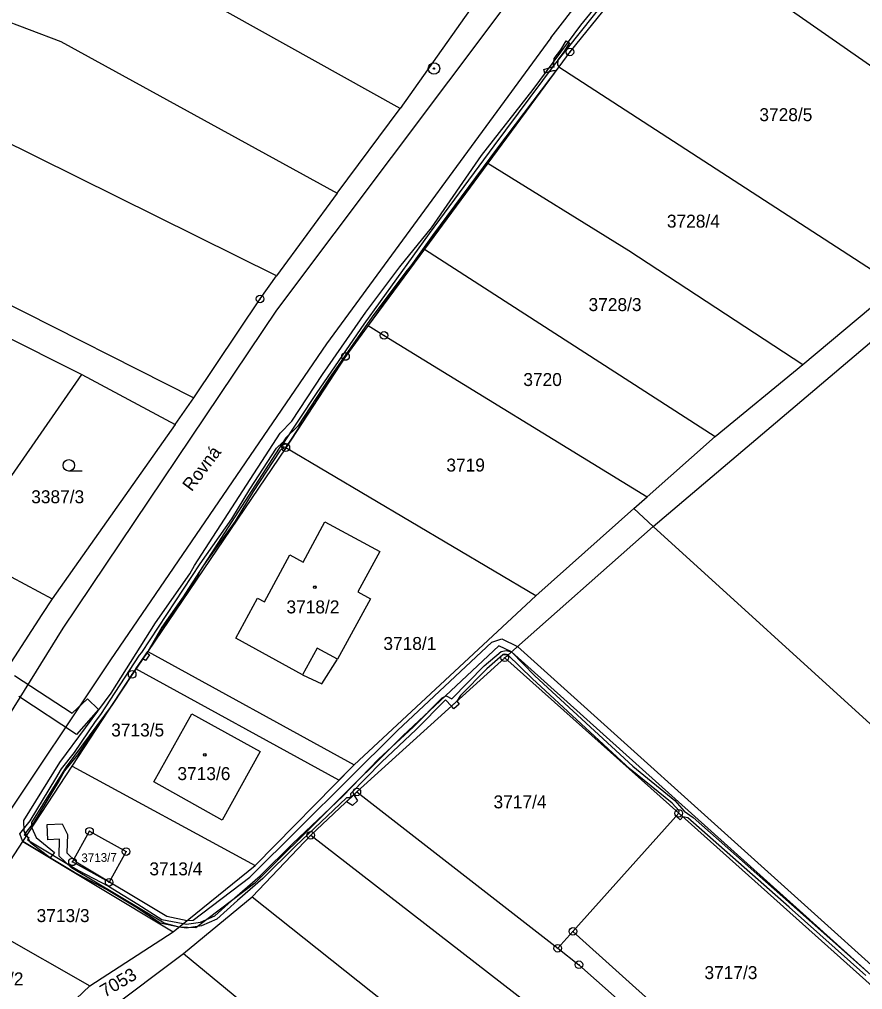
# Model space of a CAD drawing. Extents: x -593183 to -588034, y -1130415 to -1124994.
# Drawn here: x -592268.6 to -592158, y -1128640.9 to -1128513.6 of the extents above; entities that cross this region are included whole.
import ezdxf

# ---------------------------------------------------------------- set-up
doc = ezdxf.new("R2010")
doc.units = 0
for name, color, linetype in [('Vrstva 1', 7, 'Continuous'), ('Vrstva 15', 7, 'Continuous'), ('Vrstva 18', 7, 'Continuous'), ('Vrstva 19', 7, 'Continuous'), ('Vrstva 24', 7, 'Continuous'), ('Vrstva 25', 7, 'Continuous'), ('Vrstva 27', 7, 'Continuous'), ('Vrstva 4', 7, 'Continuous')]:
    doc.layers.add(name, color=color, linetype=linetype)

msp = doc.modelspace()

# ---------------------------------------------------------------- linework, layer by layer
at = {"layer": 'Vrstva 1'}
for p, q in [((-592183.06, -1128501.43), (-592196.37, -1128517.88)), ((-592183.06, -1128501.43), (-592136.79, -1128533.76)), ((-592301.19, -1128502.29), (-592263.16, -1128516.51)), ((-592218.66, -1128525.31), (-592255.87, -1128504.57)), ((-592209.44, -1128512.31), (-592218.66, -1128525.31)), ((-592263.16, -1128516.51), (-592226.91, -1128536.44)), ((-592196.37, -1128517.88), (-592197.82, -1128519.84)), ((-592197.82, -1128519.84), (-592207.12, -1128532.47)), ((-592197.82, -1128519.84), (-592153.49, -1128548.57)), ((-592226.91, -1128536.44), (-592218.66, -1128525.31)), ((-592234.89, -1128547.26), (-592277.87, -1128525.96)), ((-592215.46, -1128543.78), (-592207.12, -1128532.47)), ((-592207.12, -1128532.47), (-592188.62, -1128543.95)), ((-592226.91, -1128536.44), (-592234.89, -1128547.26)), ((-592286.92, -1128542.48), (-592245.72, -1128563.27)), ((-592215.46, -1128543.78), (-592222.84, -1128553.8)), ((-592215.46, -1128543.78), (-592177.29, -1128568.36)), ((-592188.62, -1128543.95), (-592165.79, -1128558.92)), ((-592237.03, -1128550.3), (-592234.89, -1128547.26)), ((-592185.43, -1128580.14), (-592146.62, -1128547.27)), ((-592165.79, -1128558.92), (-592153.49, -1128548.57)), ((-592245.72, -1128563.27), (-592237.03, -1128550.3)), ((-592273.91, -1128553.44), (-592260.44, -1128560.22)), ((-592222.84, -1128553.8), (-592225.82, -1128557.85)), ((-592222.84, -1128553.8), (-592220.76, -1128555.08)), ((-592220.76, -1128555.08), (-592186.23, -1128576.24)), ((-592233.65, -1128569.81), (-592225.82, -1128557.85)), ((-592177.29, -1128568.36), (-592165.79, -1128558.92)), ((-592276.39, -1128583.21), (-592260.44, -1128560.22)), ((-592260.44, -1128560.22), (-592248.17, -1128566.75)), ((-592248.17, -1128566.75), (-592245.72, -1128563.27)), ((-592248.17, -1128566.75), (-592264.34, -1128589.64)), ((-592186.23, -1128576.24), (-592177.29, -1128568.36)), ((-592233.65, -1128569.81), (-592251.78, -1128596.54)), ((-592200.83, -1128589.24), (-592233.65, -1128569.81)), ((-592187.99, -1128577.81), (-592186.23, -1128576.24)), ((-592200.83, -1128589.24), (-592187.99, -1128577.81)), ((-592187.99, -1128577.81), (-592185.43, -1128580.14)), ((-592231.36, -1128584.82), (-592228.53, -1128579.55)), ((-592228.53, -1128579.55), (-592221.32, -1128583.44)), ((-592185.43, -1128580.14), (-592204.92, -1128597.37)), ((-592185.43, -1128580.14), (-592121.56, -1128638.29)), ((-592276.39, -1128583.21), (-592264.34, -1128589.64)), ((-592236.47, -1128590.04), (-592233.11, -1128583.88)), ((-592233.11, -1128583.88), (-592231.36, -1128584.82)), ((-592221.32, -1128583.44), (-592224.21, -1128588.72)), ((-592240.22, -1128594.82), (-592237.36, -1128589.56)), ((-592237.36, -1128589.56), (-592236.47, -1128590.04)), ((-592224.68, -1128611.41), (-592200.83, -1128589.24)), ((-592224.21, -1128588.72), (-592222.54, -1128589.63)), ((-592264.34, -1128589.64), (-592265.68, -1128591.69)), ((-592222.54, -1128589.63), (-592226.88, -1128597.54)), ((-592265.68, -1128591.69), (-592274.2, -1128604.84)), ((-592231.45, -1128599.62), (-592240.22, -1128594.82)), ((-592253.82, -1128599.55), (-592251.78, -1128596.54)), ((-592251.78, -1128596.54), (-592224.68, -1128611.41)), ((-592228.91, -1128600.81), (-592226.88, -1128597.54)), ((-592204.92, -1128597.37), (-592224.33, -1128614.98)), ((-592182.09, -1128617.78), (-592204.92, -1128597.37)), ((-592261.7, -1128611.6), (-592253.82, -1128599.55)), ((-592231.45, -1128599.62), (-592228.91, -1128600.81)), ((-592250.98, -1128613.65), (-592245.98, -1128604.71)), ((-592245.98, -1128604.71), (-592237.02, -1128609.68)), ((-592237.02, -1128609.68), (-592242, -1128618.66)), ((-592268.17, -1128621.49), (-592261.7, -1128611.6)), ((-592261.7, -1128611.6), (-592237.67, -1128624.61)), ((-592237.67, -1128624.61), (-592224.68, -1128611.41)), ((-592242, -1128618.66), (-592250.98, -1128613.65)), ((-592230.38, -1128620.66), (-592224.33, -1128614.98)), ((-592224.33, -1128614.98), (-592197.96, -1128635.49)), ((-592195.97, -1128633.27), (-592182.09, -1128617.78)), ((-592182.09, -1128617.78), (-592153.73, -1128643.13)), ((-592261.65, -1128624.15), (-592259.42, -1128620.13)), ((-592259.42, -1128620.13), (-592254.61, -1128622.8)), ((-592238.07, -1128628.73), (-592230.38, -1128620.66)), ((-592230.38, -1128620.66), (-592200.42, -1128643.81)), ((-592274.81, -1128631.64), (-592268.17, -1128621.49)), ((-592268.17, -1128621.49), (-592248.43, -1128633.33)), ((-592254.61, -1128622.8), (-592256.84, -1128626.82)), ((-592256.84, -1128626.82), (-592261.65, -1128624.15)), ((-592248.43, -1128633.33), (-592237.67, -1128624.61)), ((-592247.09, -1128636.19), (-592238.07, -1128628.73)), ((-592238.07, -1128628.73), (-592208.62, -1128652.09)), ((-592274.81, -1128631.64), (-592259.39, -1128640.43)), ((-592259.39, -1128640.43), (-592248.43, -1128633.33)), ((-592197.96, -1128635.49), (-592195.97, -1128633.27)), ((-592167.56, -1128658.8), (-592195.97, -1128633.27)), ((-592258.91, -1128645.03), (-592247.09, -1128636.19)), ((-592247.09, -1128636.19), (-592216.26, -1128661.53)), ((-592197.96, -1128635.49), (-592195.18, -1128637.65)), ((-592195.18, -1128637.65), (-592169.21, -1128660.67)), ((-592268.32, -1128648.82), (-592259.39, -1128640.43))]:
    msp.add_line(p, q, dxfattribs=at)
at = {"layer": 'Vrstva 24'}
for centre, radius in [((-592196.37, -1128517.88), 0.5), ((-592196.37, -1128517.88), 0.0327), ((-592214.21, -1128520.07), 0.75), ((-592214.21, -1128520.07), 0.0903), ((-592237.03, -1128550.3), 0.5), ((-592237.03, -1128550.3), 0.0327), ((-592220.76, -1128555.08), 0.5), ((-592220.76, -1128555.08), 0.0327), ((-592225.82, -1128557.85), 0.5), ((-592225.82, -1128557.85), 0.0327), ((-592233.65, -1128569.81), 0.5), ((-592233.65, -1128569.81), 0.0327), ((-592204.92, -1128597.37), 0.5), ((-592204.92, -1128597.37), 0.0327), ((-592253.82, -1128599.55), 0.5), ((-592253.82, -1128599.55), 0.0327), ((-592224.33, -1128614.98), 0.5), ((-592224.33, -1128614.98), 0.0327), ((-592182.09, -1128617.78), 0.5), ((-592182.09, -1128617.78), 0.0327), ((-592259.42, -1128620.13), 0.5), ((-592259.42, -1128620.13), 0.0327), ((-592230.38, -1128620.66), 0.5), ((-592230.38, -1128620.66), 0.0327), ((-592254.61, -1128622.8), 0.5), ((-592261.65, -1128624.15), 0.5), ((-592254.61, -1128622.8), 0.0327), ((-592261.65, -1128624.15), 0.0327), ((-592256.84, -1128626.82), 0.5), ((-592256.84, -1128626.82), 0.0327), ((-592195.97, -1128633.27), 0.5), ((-592195.97, -1128633.27), 0.0327), ((-592197.96, -1128635.49), 0.5), ((-592197.96, -1128635.49), 0.0327), ((-592195.18, -1128637.65), 0.5), ((-592195.18, -1128637.65), 0.0327)]:
    msp.add_circle(centre, radius, dxfattribs=at)
at = {"layer": 'Vrstva 25'}
msp.add_line((-592260.38, -1128572.88), (-592262.13, -1128572.88), dxfattribs=at)
for centre, radius in [((-592262.13, -1128572.13), 0.75), ((-592229.85, -1128588.12), 0.175), ((-592229.85, -1128588.12), 0.15), ((-592244.3, -1128610.12), 0.175), ((-592244.3, -1128610.12), 0.15)]:
    msp.add_circle(centre, radius, dxfattribs=at)
at = {"layer": 'Vrstva 27'}
for p, q in [((-592183.06, -1128501.43), (-592196.37, -1128517.88)), ((-592194.93, -1128514.4), (-592186.11, -1128503.5)), ((-592190.26, -1128510.33), (-592196.37, -1128517.88)), ((-592198.41, -1128519.58), (-592191.55, -1128510.96)), ((-592201.19, -1128522.84), (-592194.93, -1128514.4)), ((-592197.57, -1128517.6), (-592196.84, -1128516.45)), ((-592196.42, -1128516.71), (-592197.15, -1128517.88)), ((-592196.84, -1128516.45), (-592196.42, -1128516.71)), ((-592198.44, -1128518.75), (-592197.57, -1128517.6)), ((-592197.15, -1128517.88), (-592197.96, -1128518.93)), ((-592196.37, -1128517.88), (-592197.82, -1128519.84)), ((-592196.37, -1128517.88), (-592197.82, -1128519.84)), ((-592198.5, -1128519.66), (-592198.44, -1128518.75)), ((-592197.96, -1128518.93), (-592198, -1128519.6)), ((-592197.82, -1128519.84), (-592207.12, -1128532.47)), ((-592206.29, -1128530.19), (-592198.41, -1128519.58)), ((-592197.82, -1128519.84), (-592205.89, -1128530.49)), ((-592199.8, -1128520.18), (-592198.66, -1128519.86)), ((-592199.66, -1128520.66), (-592199.8, -1128520.18)), ((-592198.6, -1128520.36), (-592199.66, -1128520.66)), ((-592198.66, -1128519.86), (-592198.43, -1128519.87)), ((-592198.22, -1128520.38), (-592198.6, -1128520.36)), ((-592198.43, -1128519.87), (-592198.5, -1128519.66)), ((-592197.82, -1128519.84), (-592198.22, -1128520.38)), ((-592198, -1128519.6), (-592197.82, -1128519.84)), ((-592207.99, -1128531.47), (-592201.19, -1128522.84)), ((-592214.79, -1128541.69), (-592206.29, -1128530.19)), ((-592205.89, -1128530.49), (-592214.39, -1128541.99)), ((-592214.52, -1128540.96), (-592207.99, -1128531.47)), ((-592207.12, -1128532.47), (-592215.46, -1128543.78)), ((-592218.67, -1128546.1), (-592214.52, -1128540.96)), ((-592223.36, -1128553.6), (-592214.79, -1128541.69)), ((-592214.39, -1128541.99), (-592222.84, -1128553.8)), ((-592215.46, -1128543.78), (-592217.89, -1128546.72)), ((-592223.16, -1128552.05), (-592218.67, -1128546.1)), ((-592217.89, -1128546.72), (-592222.34, -1128552.63)), ((-592228.82, -1128560.21), (-592223.16, -1128552.05)), ((-592222.34, -1128552.63), (-592228, -1128560.77)), ((-592229.54, -1128562.59), (-592223.36, -1128553.6)), ((-592222.84, -1128553.8), (-592225.82, -1128557.85)), ((-592225.82, -1128557.85), (-592233.65, -1128569.81)), ((-592232.86, -1128566.33), (-592228.82, -1128560.21)), ((-592228, -1128560.77), (-592232.08, -1128566.97)), ((-592234.25, -1128569.72), (-592229.54, -1128562.59)), ((-592234.41, -1128567.89), (-592232.86, -1128566.33)), ((-592245.65, -1128585.26), (-592234.41, -1128567.89)), ((-592232.08, -1128566.97), (-592233.63, -1128568.53)), ((-592233.63, -1128568.53), (-592244.79, -1128585.78)), ((-592234.86, -1128569.89), (-592234.1, -1128569.11)), ((-592234.1, -1128569.11), (-592233.47, -1128569.32)), ((-592238.38, -1128575.27), (-592234.86, -1128569.89)), ((-592234.46, -1128570.21), (-592237.96, -1128575.54)), ((-592233.96, -1128569.69), (-592234.46, -1128570.21)), ((-592233.8, -1128570.03), (-592234.25, -1128569.72)), ((-592233.65, -1128569.81), (-592233.96, -1128569.69)), ((-592233.65, -1128569.81), (-592233.8, -1128570.03)), ((-592233.47, -1128569.32), (-592233.65, -1128569.81)), ((-592240.72, -1128579.16), (-592238.38, -1128575.27)), ((-592237.96, -1128575.54), (-592240.3, -1128579.44)), ((-592244.9, -1128585.03), (-592240.72, -1128579.16)), ((-592240.3, -1128579.44), (-592244.48, -1128585.31)), ((-592252.56, -1128596.69), (-592244.9, -1128585.03)), ((-592244.48, -1128585.31), (-592251.78, -1128596.54)), ((-592246.24, -1128586.35), (-592245.65, -1128585.26)), ((-592250.76, -1128592.8), (-592246.24, -1128586.35)), ((-592245.38, -1128586.87), (-592249.92, -1128593.36)), ((-592244.79, -1128585.78), (-592245.38, -1128586.87)), ((-592256.56, -1128602.04), (-592250.76, -1128592.8)), ((-592249.92, -1128593.36), (-592251.78, -1128596.54)), ((-592218.98, -1128606.91), (-592206.6, -1128595.32)), ((-592205.68, -1128595.82), (-592218.28, -1128607.63)), ((-592206.6, -1128595.32), (-592205.31, -1128594.89)), ((-592204.05, -1128596.6), (-592205.68, -1128595.82)), ((-592205.31, -1128594.89), (-592203.23, -1128595.88)), ((-592203.23, -1128595.88), (-592165.13, -1128630.17)), ((-592257.91, -1128604.8), (-592252.84, -1128597.02)), ((-592251.78, -1128596.54), (-592253.82, -1128599.55)), ((-592253.33, -1128598.83), (-592251.78, -1128596.54)), ((-592252.84, -1128597.02), (-592252.56, -1128596.69)), ((-592252.44, -1128597.51), (-592251.91, -1128596.73)), ((-592251.91, -1128596.73), (-592252.44, -1128597.51)), ((-592251.55, -1128596.97), (-592252.08, -1128597.75)), ((-592251.78, -1128596.54), (-592251.91, -1128596.73)), ((-592251.91, -1128596.73), (-592251.55, -1128596.97)), ((-592251.78, -1128596.54), (-592224.68, -1128611.41)), ((-592207.61, -1128598.45), (-592205.38, -1128596.55)), ((-592205.16, -1128597.01), (-592207.27, -1128598.81)), ((-592205.38, -1128596.55), (-592204.75, -1128596.43)), ((-592204.5, -1128597), (-592205.16, -1128597.01)), ((-592204.75, -1128596.43), (-592204.05, -1128596.6)), ((-592201.31, -1128600.11), (-592204.5, -1128597)), ((-592165.79, -1128630.91), (-592204.05, -1128596.6)), ((-592204.05, -1128596.6), (-592200.97, -1128599.75)), ((-592252.44, -1128597.51), (-592253.82, -1128599.55)), ((-592252.08, -1128597.75), (-592252.44, -1128597.51)), ((-592211.88, -1128602.76), (-592207.61, -1128598.45)), ((-592269.27, -1128599.71), (-592261.71, -1128604.66)), ((-592253.82, -1128599.55), (-592257.51, -1128605.08)), ((-592253.82, -1128599.55), (-592256.43, -1128603.54)), ((-592226.68, -1128613.45), (-592253.33, -1128598.83)), ((-592207.27, -1128598.81), (-592210.74, -1128602.33)), ((-592188.44, -1128611.98), (-592201.31, -1128600.11)), ((-592200.97, -1128599.75), (-592188.12, -1128611.6)), ((-592263.32, -1128611.13), (-592256.56, -1128602.04)), ((-592261.13, -1128607.42), (-592268.69, -1128602.47)), ((-592256.43, -1128603.54), (-592262.5, -1128611.69)), ((-592261.71, -1128604.66), (-592259.7, -1128602.77)), ((-592259.7, -1128602.77), (-592258.24, -1128604.15)), ((-592216.89, -1128606.42), (-592213.12, -1128602.62)), ((-592212.69, -1128602.89), (-592216.55, -1128606.78)), ((-592213.12, -1128602.62), (-592212.59, -1128602.38)), ((-592211.91, -1128603.72), (-592212.69, -1128602.89)), ((-592212.59, -1128602.38), (-592211.88, -1128602.76)), ((-592211.22, -1128603.08), (-592211.91, -1128603.72)), ((-592211.91, -1128603.72), (-592211.22, -1128603.08)), ((-592210.88, -1128603.46), (-592211.58, -1128604.09)), ((-592210.74, -1128602.33), (-592211.22, -1128603.08)), ((-592211.22, -1128603.08), (-592210.88, -1128603.46)), ((-592258.24, -1128604.15), (-592261.13, -1128607.42)), ((-592258.63, -1128605.75), (-592257.91, -1128604.8)), ((-592211.58, -1128604.09), (-592211.91, -1128603.72)), ((-592261.4, -1128609.79), (-592258.63, -1128605.75)), ((-592258.23, -1128606.05), (-592261, -1128610.09)), ((-592257.51, -1128605.08), (-592258.23, -1128606.05)), ((-592238.39, -1128626.18), (-592218.98, -1128606.91)), ((-592221.47, -1128610.69), (-592216.89, -1128606.42)), ((-592216.55, -1128606.78), (-592221.11, -1128611.05)), ((-592218.28, -1128607.63), (-592237.73, -1128626.94)), ((-592263.1, -1128611.93), (-592261.4, -1128609.79)), ((-592268.05, -1128618.73), (-592263.32, -1128611.13)), ((-592261, -1128610.09), (-592262.68, -1128612.21)), ((-592226.19, -1128615.55), (-592221.47, -1128610.69)), ((-592221.11, -1128611.05), (-592225.18, -1128615.23)), ((-592262.5, -1128611.69), (-592267.03, -1128618.99)), ((-592263.82, -1128613.23), (-592263.1, -1128611.93)), ((-592262.68, -1128612.21), (-592263.38, -1128613.49)), ((-592224.68, -1128611.41), (-592226.68, -1128613.45)), ((-592182.93, -1128616.47), (-592188.44, -1128611.98)), ((-592188.12, -1128611.6), (-592182.59, -1128616.11)), ((-592267.21, -1128618.75), (-592263.82, -1128613.23)), ((-592263.38, -1128613.49), (-592266.79, -1128619.03)), ((-592232.73, -1128621.73), (-592226.19, -1128615.55)), ((-592225.67, -1128615.75), (-592232.39, -1128622.09)), ((-592225.69, -1128616.26), (-592224.73, -1128615.36)), ((-592224.92, -1128616.76), (-592225.69, -1128616.26)), ((-592225.3, -1128615.76), (-592225.67, -1128615.75)), ((-592225.12, -1128615.61), (-592225.3, -1128615.76)), ((-592225.18, -1128615.23), (-592225.12, -1128615.61)), ((-592224.26, -1128616.14), (-592224.92, -1128616.76)), ((-592224.73, -1128615.36), (-592224.26, -1128616.14)), ((-592182.59, -1128616.11), (-592181.35, -1128617.48)), ((-592182.03, -1128617.47), (-592182.93, -1128616.47)), ((-592182.09, -1128617.78), (-592182.03, -1128617.47)), ((-592181.35, -1128617.48), (-592180.17, -1128618.34)), ((-592268.55, -1128620.49), (-592267.21, -1128618.75)), ((-592267.98, -1128620.12), (-592268.05, -1128618.73)), ((-592182.41, -1128618.14), (-592182.09, -1128617.78)), ((-592181.88, -1128618.62), (-592182.41, -1128618.14)), ((-592181.56, -1128618.26), (-592182.09, -1128617.78)), ((-592182.09, -1128617.78), (-592181.56, -1128618.26)), ((-592181.56, -1128618.26), (-592181.88, -1128618.62)), ((-592180.89, -1128618.37), (-592181.56, -1128618.26)), ((-592167.61, -1128630.11), (-592180.89, -1128618.37)), ((-592180.17, -1128618.34), (-592167.27, -1128629.73)), ((-592266.79, -1128619.03), (-592267.98, -1128620.58)), ((-592267.03, -1128618.99), (-592267, -1128619.7)), ((-592267, -1128619.7), (-592266.4, -1128620.95)), ((-592264.99, -1128619.26), (-592262.99, -1128619.16)), ((-592264.89, -1128621.26), (-592264.99, -1128619.26)), ((-592262.99, -1128619.16), (-592262.31, -1128620.54)), ((-592268.17, -1128621.49), (-592268.55, -1128620.49)), ((-592267.66, -1128620.71), (-592267.98, -1128620.12)), ((-592267.98, -1128620.58), (-592267.7, -1128620.77)), ((-592267.7, -1128620.77), (-592267.39, -1128620.97)), ((-592267.11, -1128621.7), (-592267.66, -1128620.71)), ((-592267.39, -1128620.97), (-592267.57, -1128621.25)), ((-592267.57, -1128621.25), (-592260.86, -1128625.27)), ((-592266.4, -1128620.95), (-592264.02, -1128622.94)), ((-592263.34, -1128621.18), (-592264.89, -1128621.26)), ((-592263.42, -1128623.4), (-592263.34, -1128621.18)), ((-592262.31, -1128620.54), (-592262.4, -1128622.98)), ((-592261.39, -1128625.56), (-592268.17, -1128621.49)), ((-592264.6, -1128623.63), (-592267.11, -1128621.7)), ((-592237.01, -1128625.99), (-592232.73, -1128621.73)), ((-592232.39, -1128622.09), (-592236.67, -1128626.35)), ((-592264.02, -1128622.94), (-592264.6, -1128623.63)), ((-592261.77, -1128624.94), (-592263.42, -1128623.4)), ((-592262.4, -1128622.98), (-592261.17, -1128624.14)), ((-592249.64, -1128632.21), (-592261.77, -1128624.94)), ((-592261.17, -1128624.14), (-592249.26, -1128631.27)), ((-592257.18, -1128627.77), (-592261.39, -1128625.56)), ((-592260.86, -1128625.27), (-592256.94, -1128627.33)), ((-592245.81, -1128631.81), (-592238.39, -1128626.18)), ((-592240.35, -1128628.85), (-592237.01, -1128625.99)), ((-592236.67, -1128626.35), (-592240.01, -1128629.23)), ((-592256.94, -1128627.33), (-592253.09, -1128629.68)), ((-592237.73, -1128626.94), (-592245.45, -1128632.79)), ((-592253.35, -1128630.1), (-592257.18, -1128627.77)), ((-592242.98, -1128631.25), (-592240.35, -1128628.85)), ((-592250.14, -1128632.21), (-592253.35, -1128630.1)), ((-592253.09, -1128629.68), (-592249.94, -1128631.73)), ((-592240.01, -1128629.23), (-592242.7, -1128631.67)), ((-592157.54, -1128639.04), (-592167.61, -1128630.11)), ((-592167.27, -1128629.73), (-592157.22, -1128638.66)), ((-592165.13, -1128630.17), (-592127.68, -1128664.07)), ((-592249.26, -1128631.27), (-592246.62, -1128631.86)), ((-592244.85, -1128632.08), (-592242.98, -1128631.25)), ((-592128.34, -1128664.81), (-592165.79, -1128630.91)), ((-592247.65, -1128632.7), (-592250.14, -1128632.21)), ((-592249.94, -1128631.73), (-592247.11, -1128632.26)), ((-592247.65, -1128632.7), (-592249.64, -1128632.21)), ((-592245.45, -1128632.79), (-592247.65, -1128632.7)), ((-592246.68, -1128632.84), (-592247.65, -1128632.7)), ((-592247.11, -1128632.26), (-592246.68, -1128632.34)), ((-592246.68, -1128632.34), (-592244.85, -1128632.08)), ((-592244.71, -1128632.56), (-592246.68, -1128632.84)), ((-592246.62, -1128631.86), (-592245.81, -1128631.81)), ((-592242.7, -1128631.67), (-592244.71, -1128632.56))]:
    msp.add_line(p, q, dxfattribs=at)
at = {"layer": 'Vrstva 4'}
for p, q in [((-592198.89, -1128516.04), (-592168.03, -1128476.56)), ((-592204.78, -1128511.73), (-592234.87, -1128551.75)), ((-592198.89, -1128516.04), (-592228.32, -1128556.17)), ((-592234.87, -1128551.75), (-592262.93, -1128593.51)), ((-592228.32, -1128556.17), (-592256.67, -1128597.66)), ((-592262.93, -1128593.51), (-592288.76, -1128635)), ((-592229.52, -1128596.1), (-592231.45, -1128599.62)), ((-592226.88, -1128597.54), (-592229.52, -1128596.1)), ((-592256.67, -1128597.66), (-592284.25, -1128638.87))]:
    msp.add_line(p, q, dxfattribs=at)

# ---------------------------------------------------------------- texts
at = {"layer": 'Vrstva 15'}
msp.add_text('Rovná', height=1.7, rotation=53.0429, dxfattribs=at).set_placement((-592246.01, -1128575.66))
at = {"layer": 'Vrstva 18'}
for s, p in [('3728/5', (-592171.5, -1128526.97)), ('3728/4', (-592183.64, -1128540.94)), ('3728/3', (-592193.92, -1128551.89)), ('3720', (-592202.48, -1128561.72)), ('3719', (-592212.58, -1128572.94)), ('3387/3', (-592267.07, -1128577.1)), ('3718/1', (-592220.85, -1128596.35)), ('3713/5', (-592256.57, -1128607.7)), ('3717/4', (-592206.39, -1128617.13)), ('3713/4', (-592251.56, -1128625.92)), ('3713/3', (-592266.36, -1128632.05)), ('3717/3', (-592178.71, -1128639.53)), ('3713/2', (-592275.04, -1128640.36))]:
    msp.add_text(s, height=1.7, dxfattribs=at).set_placement(p)
for s, height, rotation, p in [('3713/7', 1.14, 1.1017, (-592260.48, -1128624.2)), ('7053', 1.7, 30.4187, (-592257.41, -1128641.98))]:
    msp.add_text(s, height=height, rotation=rotation, dxfattribs=at).set_placement(p)
at = {"layer": 'Vrstva 19'}
for s, p in [('3718/2', (-592233.57, -1128591.55)), ('3713/6', (-592247.88, -1128613.42))]:
    msp.add_text(s, height=1.7, dxfattribs=at).set_placement(p)

doc.saveas('drawing.dxf')
